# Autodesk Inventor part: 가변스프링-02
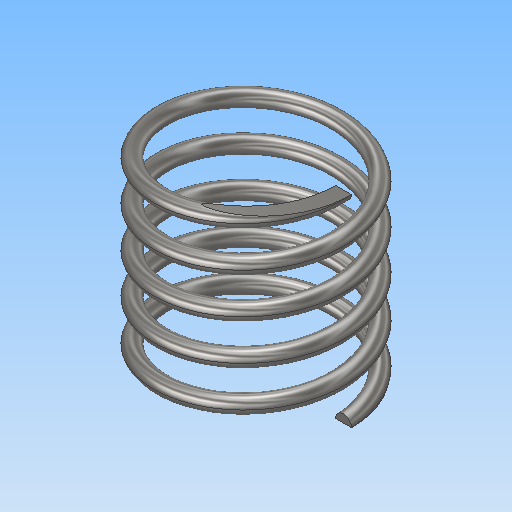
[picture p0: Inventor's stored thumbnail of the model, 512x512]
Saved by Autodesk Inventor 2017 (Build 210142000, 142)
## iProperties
Part Number: 가변스프링-02
Material: 강철, 연강
Document SubType Name: Modeling
Designer: MRC
Density: 7.85 g/cm^3
Appearance: 반연마
Mass: 8.38002 g
Surface Area: 21.6558 cm^2
Volume: 1.06752 cm^3
Author: MRC
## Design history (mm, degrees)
sketch "스케치1"
  geometry: L1 (0, 0)-(11, 0); L2 (11, 0)-(11, 25.358); L3 (11, 25.358)-(0, 25.358); L4 (0, 25.358)-(0, 0); C1 r 1 at (11, 0)
  constraints: 8 end point, 2 parallel, 1 centre point, 1 coincident, 1 horizontal, 1 perpendicular
  dimensions: "d0" = 25.35829 distance of L3.end L1.start (derived); "d1" = 22 diameter of L2 L4; "d2" = 2 diameter of C1
feature "코일1" sketch "스케치1" pitch "d3" = 10; turns "d5" = 5; dims "d4" = 25.35829 (= d0), "d6" = 0, angle "d7" = 90 deg, angle "d8" = 90 deg, "d9" = 0, "d10" = 0
sketch "스케치2"
  geometry: L1 (25.358, 17.383)-(0, 17.383); L2 (0, 17.383)-(0, -17.383); L3 (0, -17.383)-(25.358, -17.383); L4 (25.358, -17.383)-(25.358, 17.383); 2 further points
  constraints: 8 end point, 2 parallel, 1 coincident, 1 horizontal, 1 midpoint, 1 perpendicular
  dimensions: "d11" = 25.35829 distance of L2.end L3.end (= d0); "d12" = 34.76604 distance of L3.end L1.start
extrude "돌출1" sketch "스케치2" stored distance "d13" = 47.75; taper "d14" = 0 deg
node "솔리드1"
